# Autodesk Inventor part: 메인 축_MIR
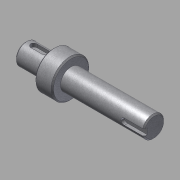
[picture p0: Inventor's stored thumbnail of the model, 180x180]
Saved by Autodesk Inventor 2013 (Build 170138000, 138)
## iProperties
Created: 2014-10
Part Number: 메인 축_MIR
Material: 강철, 연강
Document SubType Name: Modeling
Designer: Administrator
Mass: 230.24 g
Surface Area: 74.3518 cm^2
Volume: 29.2926 cm^3
Density: 7.86 g/cm^3
Author: SeoGD™ [www.esajin.kr]
Revision Number: 1
d0: 17.000 mm
d1: 30.000 mm
d2: 22.000 mm
d5: 17.000 mm
d6: 1.000 mm
d9: 5.000 mm
d10: 14.000 mm
d11: 4.000 mm
d12: 3.000 mm
d13: 0.00 deg
d14: 5.000 mm
d15: 18.000 mm
d16: 3.000 mm
d17: 0.00 deg
d19: 80.000 mm
d3: 65.997 mm
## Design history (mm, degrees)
node "메인 축"
  sketch "스케치1"
    geometry: L1 (-46.5, -69.749)-(-46.5, -45.251) reference; L2 (-46.5, -72.5)-(-46.5, -66) reference; L3 (-32.497, -72.5)-(-32.497, -66) reference; L4 (-32.497, -35)-(-32.497, -80) reference; L5 (-10.497, -57.5)-(-112.497, -57.5) reference; L6 (-10.497, -66)-(-32.497, -66) reference; L7 (-32.497, -72.5)-(-46.5, -72.5) reference; L8 (-46.5, -66)-(-112.497, -66) reference; L9 (-112.497, -66)-(-112.497, -57.5) reference; L10 (-10.497, -66)-(-10.497, -57.5) reference; 3 further points
  sketch "스케치2"
    geometry: L1 (11, -7.5)-(11, 7.5) reference; L2 (4.5, 2.5)-(-4.5, 2.5) reference; L3 (-4.5, -2.5)-(4.5, -2.5) reference; A1 r 2.5 centre (-4.5, 0) between (-4.5, 2.5) and (-4.5, -2.5) reference; A2 r 2.5 centre (4.5, 0) between (4.5, -2.5) and (4.5, 2.5) reference; 2 further points
  sketch "스케치3"
    geometry: L1 (-32.998, 7.5)-(-32.998, -7.5) reference; L2 (-32.998, 2.5)-(-17.498, 2.5) reference; L3 (-17.498, -2.5)-(-32.998, -2.5) reference; A1 r 2.5 centre (-17.498, 0) between (-17.498, -2.5) and (-17.498, 2.5) reference; 2 further points
  node "작업 평면1"
  node "작업 평면2"
feature "솔리드1::메인 축"
tag "피쳐 태그1"
node "솔리드1"
other parameters: "d0" = 10, "d0_1" = 17, "d1" = 30, "d2" = 22, "d5" = 17, "d6" = 1, "d9" = 5, "d10" = 14, "d11" = 4, "d12" = 3, "d13" = 0 deg, "d14" = 5, "d15" = 18, "d16" = 3, "d17" = 0 deg, "d19" = 80, "d3" = 65.99692
